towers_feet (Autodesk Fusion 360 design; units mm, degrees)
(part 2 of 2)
align "Align2"
move "Move19"
align "Align3"
move "Move20"
move "Move21"
align "Align4"
move "Move22"
align "Align5"
move "Move23"
align "Align6"
move "Move24"
align "Align7"
move "Move25"
move "Move26"
move "Move27"
move "Move28"
align "Align8"
align "Align9"
move "Move29"
align "Align10"
move "Move30"
align "Align11"
move "Move31"
align "Align12"
move "Move32"
move "Move33"
move "Move34"
move "Move35"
